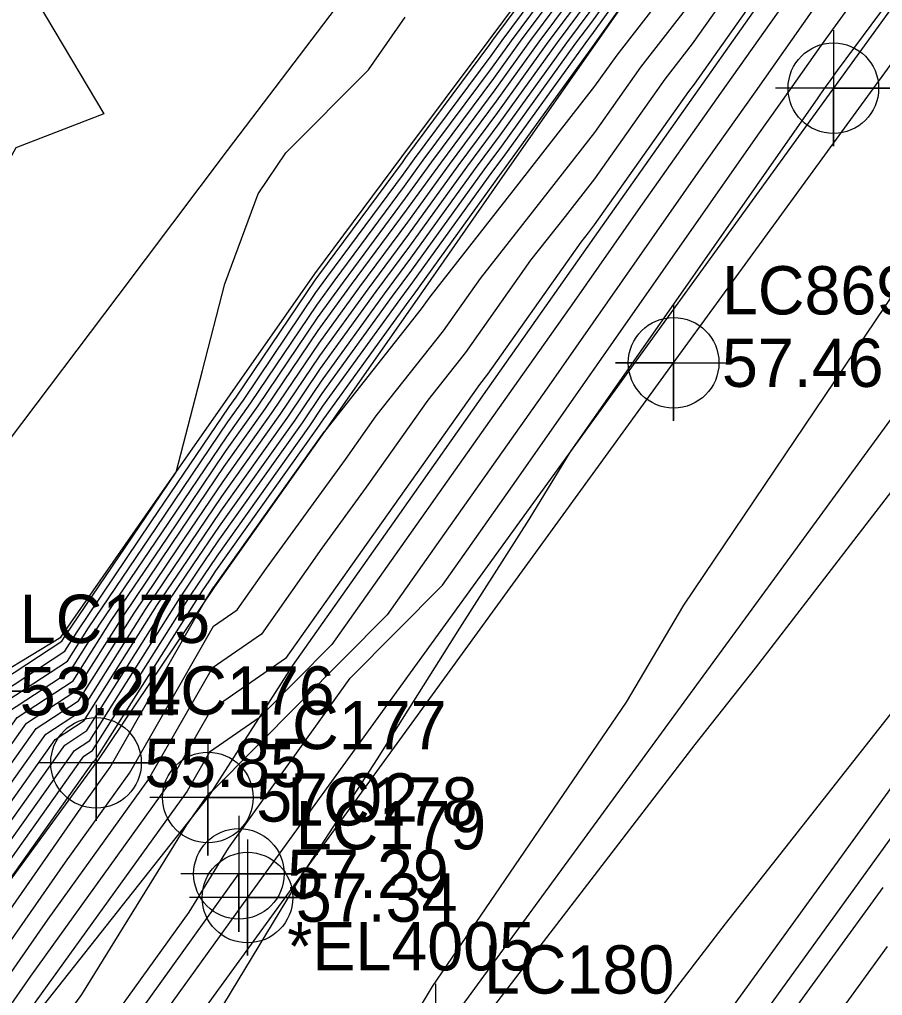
# Model space of a CAD drawing. Extents: x 2188792 to 2191981, y 386090 to 389710.
# Drawn here: x 2190183 to 2190227.7, y 387712.4 to 387762.9 of the extents above; entities that cross this region are included whole.
import ezdxf

# ---------------------------------------------------------------- set-up
doc = ezdxf.new("R2010")
doc.units = 0
for name, color, linetype in [('DTM Contours Major', 7, 'Continuous'), ('DTM Contours Minor', 7, 'Continuous'), ('Exist DTM Breakline', 7, 'Continuous'), ('Exist DTM Breakline Cogo Comment', 7, 'Continuous'), ('Exist DTM Breakline Cogo Elevation', 7, 'Continuous'), ('Exist DTM Breakline Cogo Number', 7, 'Continuous'), ('Exist DTM Breakline Cogo Point CELL', 7, 'Continuous'), ('Exist Roads EOP', 7, 'Continuous'), ('Exist Roads EOP Cogo Elevation', 7, 'Continuous'), ('Exist Roads EOP Cogo Number', 7, 'Continuous'), ('Exist Roads EOP Cogo Point CELL', 7, 'Continuous'), ('Exist Roads EOT', 7, 'Continuous'), ('Exist Roads EOT Cogo Elevation', 7, 'Continuous'), ('Exist Roads EOT Cogo Number', 7, 'Continuous'), ('Exist Roads EOT Cogo Point CELL', 7, 'Continuous'), ('PH Exist DTM Breakline', 7, 'Continuous')]:
    doc.layers.add(name, color=color, linetype=linetype)

msp = doc.modelspace()

# ---------------------------------------------------------------- linework, layer by layer
at = {"layer": 'DTM Contours Major'}
for points in [[(2190133.87, 387655.746), (2190142.758, 387668.494), (2190149.725, 387678.572), (2190158.031, 387690.49), (2190165.915, 387701.499), (2190174.768, 387715.425), (2190179.91, 387723.513), (2190182.41, 387727.03), (2190185.657, 387729.153), (2190187.188, 387731.574), (2190190.393, 387736.313), (2190193.755, 387741.283), (2190194.999, 387743.03), (2190198.413, 387748.085), (2190199.369, 387749.409), (2190202.959, 387754.245), (2190203.928, 387755.588), (2190207.505, 387760.407), (2190208.488, 387761.771), (2190212.052, 387766.571)], [(2190140.89, 387656.284), (2190146.901, 387665.291), (2190154.576, 387676.484), (2190161.876, 387687.503), (2190167.02, 387694.554), (2190179.211, 387712.029), (2190186.322, 387722.222), (2190187.723, 387724.17), (2190192.656, 387732.814), (2190193.092, 387733.504), (2190193.112, 387733.532), (2190193.132, 387733.563), (2190198.6, 387741.243), (2190198.822, 387741.549), (2190198.826, 387741.554), (2190203.838, 387747.893), (2190204.285, 387748.526), (2190208.885, 387754.4), (2190212.816, 387759.42), (2190213.956, 387761.034), (2190217.629, 387765.763)], [(2190127.342, 387642.535), (2190141.894, 387663.608), (2190144.416, 387667.226), (2190156.401, 387684.564), (2190159.664, 387689.245), (2190172.917, 387707.751), (2190176.812, 387713.878), (2190179.075, 387717.436), (2190184.882, 387725.608), (2190186.377, 387726.585), (2190190.14, 387732.539), (2190191.753, 387734.923), (2190193.444, 387737.423), (2190196.91, 387742.291), (2190198.616, 387744.818), (2190201.494, 387748.804), (2190203.232, 387751.146), (2190206.18, 387755.233), (2190207.853, 387757.486), (2190210.876, 387761.68), (2190212.479, 387763.839)], [(2190224.046, 387763.305), (2190221.103, 387759.138), (2190218.148, 387754.954), (2190210.306, 387743.744), (2190207.567, 387739.867), (2190204.816, 387735.972), (2190202.053, 387732.06), (2190192.984, 387722.924), (2190192.787, 387722.788), (2190192.698, 387722.633), (2190191.665, 387721.196), (2190186.235, 387712.417), (2190183.515, 387708.629), (2190176.737, 387698.177), (2190166.485, 387683.901), (2190161.021, 387675.685), (2190151.311, 387661.898), (2190146.496, 387654.704)], [(2190170.079, 387637.175), (2190184.662, 387656.987), (2190185.776, 387658.366), (2190186.967, 387659.84), (2190188.243, 387661.42), (2190197.783, 387674.451), (2190199.179, 387676.153), (2190200.634, 387677.925), (2190213.842, 387695.932), (2190215.385, 387697.799), (2190216.994, 387699.745), (2190218.456, 387701.786), (2190227.964, 387714.893)]]:
    msp.add_lwpolyline(points, dxfattribs=at)
at = {"layer": 'DTM Contours Minor'}
for points in [[(2190236.814, 387775.68), (2190225.355, 387760.234), (2190225.027, 387759.78), (2190224.687, 387759.299), (2190224.346, 387758.816), (2190211.532, 387740.5), (2190209.395, 387737.001), (2190205.804, 387731.38), (2190201.546, 387724.601), (2190197.585, 387718.517), (2190188.492, 387703.504), (2190186.127, 387699.811), (2190174.426, 387684.183), (2190172.877, 387681.712), (2190156.767, 387660.35), (2190155.266, 387658.13), (2190146.358, 387642.623)], [(2190180.149, 387770.153), (2190187.392, 387758.002), (2190182.84, 387756.231), (2190180.027, 387751.126), (2190177.184, 387749.402), (2190173.952, 387743.892), (2190171.784, 387742.264), (2190161.749, 387741.818), (2190161.042, 387741.424), (2190160.579, 387741.13), (2190160.248, 387740.921), (2190159.124, 387741.951), (2190160.03, 387742.776), (2190160.137, 387742.776), (2190160.326, 387742.976), (2190168.506, 387745.64), (2190168.822, 387746.292), (2190169.721, 387748.153), (2190173.552, 387753.544), (2190174.832, 387756.785), (2190178.103, 387761.247), (2190180.12, 387770.172)], [(2190131.832, 387646.855), (2190145.085, 387666.714), (2190145.132, 387666.783), (2190145.306, 387667.046), (2190159.072, 387686.961), (2190160.317, 387688.747), (2190175.718, 387710.251), (2190177.63, 387713.259), (2190178.74, 387715.006), (2190185.871, 387725.04), (2190186.665, 387725.558), (2190191.321, 387732.925), (2190192.296, 387734.367), (2190193.319, 387735.879), (2190197.674, 387741.996), (2190198.698, 387743.511), (2190202.344, 387748.563), (2190203.342, 387749.906), (2190207.081, 387755.091), (2190207.992, 387756.318), (2190211.831, 387761.644), (2190212.65, 387762.746), (2190216.595, 387768.222)], [(2190134.852, 387649.998), (2190145.69, 387666.24), (2190148.28, 387670.017), (2190157.797, 387684.383), (2190160.408, 387688.159), (2190160.644, 387688.498), (2190177.118, 387711.502), (2190178.039, 387712.95), (2190178.573, 387713.791), (2190186.366, 387724.755), (2190186.809, 387725.045), (2190191.911, 387733.118), (2190192.568, 387734.089), (2190193.257, 387735.107), (2190198.056, 387741.848), (2190198.738, 387742.858), (2190202.769, 387748.442), (2190203.396, 387749.287), (2190207.532, 387755.02), (2190208.062, 387755.733), (2190212.309, 387761.625), (2190212.735, 387762.199), (2190217.101, 387768.26)], [(2190243.271, 387768.482), (2190235.055, 387757.448), (2190228.888, 387749.601), (2190217.395, 387732.559), (2190214.432, 387727.547), (2190204.397, 387712.818), (2190202.052, 387708.946), (2190187.254, 387685.834), (2190204.7, 387708.079), (2190206.378, 387710.213), (2190218.002, 387725.342), (2190221.117, 387729.294), (2190235.868, 387748.461), (2190239.037, 387752.903), (2190247.964, 387765.605)], [(2190130.661, 387652.601), (2190142.095, 387669.001), (2190147.054, 387676.176), (2190157.378, 387690.988), (2190163.115, 387698.998), (2190173.951, 387716.044), (2190180.244, 387725.943), (2190181.421, 387727.599), (2190185.37, 387730.18), (2190186.007, 387731.189), (2190189.85, 387736.869), (2190193.88, 387742.827), (2190194.235, 387743.326), (2190198.332, 387749.392), (2190198.519, 387749.651), (2190202.849, 387755.484), (2190203.027, 387755.731), (2190207.365, 387761.575), (2190207.533, 387761.808), (2190211.881, 387767.664)], [(2190132.265, 387654.173), (2190142.426, 387668.748), (2190148.389, 387677.374), (2190157.705, 387690.739), (2190164.515, 387700.248), (2190174.36, 387715.734), (2190180.077, 387724.728), (2190181.915, 387727.314), (2190185.514, 387729.667), (2190186.598, 387731.382), (2190190.121, 387736.591), (2190193.817, 387742.055), (2190194.617, 387743.178), (2190198.373, 387748.739), (2190198.944, 387749.53), (2190202.904, 387754.865), (2190203.477, 387755.659), (2190207.435, 387760.991), (2190208.011, 387761.79), (2190211.966, 387767.118)], [(2190221.595, 387766.921), (2190217.846, 387761.61), (2190216.427, 387759.784), (2190212.792, 387754.636), (2190211.267, 387752.689), (2190209.484, 387750.412), (2190206.117, 387745.647), (2190204.166, 387743.179), (2190200.98, 387738.67), (2190198.686, 387735.506), (2190195.547, 387731.064), (2190192.994, 387729.304), (2190189.713, 387723.555), (2190184.502, 387716.311), (2190180.69, 387710.847), (2190174.155, 387701.479), (2190163.184, 387686.443), (2190160.871, 387682.952), (2190148.112, 387664.343), (2190146.929, 387662.57), (2190131.187, 387639.658)], [(2190222.869, 387766.495), (2190217.954, 387759.534), (2190217.663, 387759.159), (2190212.779, 387752.243), (2190212.459, 387751.834), (2190212.083, 387751.355), (2190207.257, 387744.523), (2190206.837, 387743.992), (2190202.059, 387737.231), (2190201.553, 387736.533), (2190196.795, 387729.8), (2190192.925, 387727.132), (2190190.708, 387723.248), (2190183.592, 387713.356), (2190181.43, 387710.256), (2190177.722, 387704.941), (2190164.766, 387687.184), (2190164.244, 387686.379), (2190163.885, 387685.879), (2190150.972, 387666.462), (2190148.998, 387663.661), (2190136.26, 387644.629)], [(2190125.988, 387643.58), (2190135.475, 387657.318), (2190143.09, 387668.24), (2190151.06, 387679.771), (2190158.358, 387690.241), (2190167.316, 387702.749), (2190175.177, 387715.116), (2190179.743, 387722.297), (2190182.904, 387726.746), (2190185.801, 387728.64), (2190187.778, 387731.767), (2190190.665, 387736.035), (2190193.693, 387740.511), (2190195.381, 387742.882), (2190198.454, 387747.432), (2190199.794, 387749.288), (2190203.013, 387753.625), (2190204.378, 387755.517), (2190207.574, 387759.823), (2190208.966, 387761.753), (2190212.137, 387766.025)], [(2190126.326, 387643.319), (2190137.08, 387658.89), (2190143.421, 387667.987), (2190152.395, 387680.969), (2190158.684, 387689.992), (2190168.716, 387703.999), (2190175.586, 387714.806), (2190179.576, 387721.082), (2190183.399, 387726.461), (2190185.945, 387728.126), (2190188.369, 387731.96), (2190190.937, 387735.757), (2190193.631, 387739.739), (2190195.764, 387742.735), (2190198.495, 387746.778), (2190200.219, 387749.167), (2190203.068, 387753.005), (2190204.829, 387755.446), (2190207.644, 387759.238), (2190209.443, 387761.735), (2190212.223, 387765.478)], [(2190223.556, 387765.067), (2190219.311, 387759.057), (2190215.049, 387753.023), (2190211.731, 387748.279), (2190207.569, 387742.387), (2190203.388, 387736.468), (2190199.189, 387730.522), (2190195.427, 387726.733), (2190192.856, 387724.96), (2190191.703, 387722.941), (2190182.683, 387710.4), (2190182.169, 387709.665), (2190181.29, 387708.404), (2190178.215, 387704.19), (2190170.49, 387692.278), (2190165.185, 387684.89), (2190155.996, 387671.074), (2190150.155, 387662.779), (2190141.378, 387649.667)], [(2190126.665, 387643.058), (2190138.684, 387660.463), (2190143.753, 387667.733), (2190153.731, 387682.167), (2190159.011, 387689.743), (2190170.117, 387705.25), (2190175.995, 387714.497), (2190179.409, 387719.867), (2190183.893, 387726.177), (2190186.089, 387727.612), (2190188.959, 387732.153), (2190191.209, 387735.479), (2190193.568, 387738.967), (2190196.146, 387742.587), (2190198.535, 387746.125), (2190200.644, 387749.046), (2190203.123, 387752.386), (2190205.279, 387755.375), (2190207.714, 387758.654), (2190209.921, 387761.717), (2190212.308, 387764.932)], [(2190127.003, 387642.796), (2190140.289, 387662.035), (2190144.085, 387667.479), (2190155.066, 387683.366), (2190159.337, 387689.494), (2190171.517, 387706.5), (2190176.404, 387714.187), (2190179.242, 387718.652), (2190184.388, 387725.893), (2190186.233, 387727.099), (2190189.55, 387732.346), (2190191.481, 387735.201), (2190193.506, 387738.195), (2190196.528, 387742.439), (2190198.576, 387745.471), (2190201.069, 387748.925), (2190203.177, 387751.766), (2190205.73, 387755.304), (2190207.783, 387758.07), (2190210.399, 387761.698), (2190212.393, 387764.385)], [(2190130.575, 387640.019), (2190143.91, 387659.427), (2190147.506, 387664.817), (2190157.723, 387679.718), (2190162.53, 387686.973), (2190170.587, 387698.016), (2190179.951, 387711.438), (2190185.412, 387719.266), (2190188.718, 387723.862), (2190193.063, 387731.476), (2190194.3, 387732.329), (2190195.82, 387734.479), (2190199.901, 387740.11), (2190201.496, 387742.367), (2190204.978, 387746.77), (2190206.884, 387749.469), (2190210.076, 387753.544), (2190212.804, 387757.028), (2190215.192, 387760.409), (2190217.737, 387763.686)], [(2190137.871, 387653.141), (2190146.296, 387665.766), (2190151.428, 387673.251), (2190161.221, 387688.033), (2190163.453, 387691.092), (2190178.471, 387712.62), (2190180.248, 387715.167), (2190186.86, 387724.471), (2190186.953, 387724.531), (2190192.502, 387733.311), (2190192.84, 387733.81), (2190193.194, 387734.335), (2190198.438, 387741.7), (2190198.779, 387742.204), (2190203.194, 387748.321), (2190203.451, 387748.667), (2190207.983, 387754.949), (2190208.131, 387755.149), (2190212.786, 387761.607), (2190212.82, 387761.653), (2190214.159, 387763.512)], [(2190139.311, 387642.336), (2190151.615, 387659.742), (2190152.468, 387661.017), (2190166.045, 387680.296), (2190167.785, 387682.911), (2190182.984, 387704.076), (2190185.135, 387707.394), (2190191.803, 387716.678), (2190193.847, 387719.984), (2190200.144, 387728.79), (2190204.917, 387733.598), (2190206.245, 387735.476), (2190207.566, 387737.347), (2190208.881, 387739.209), (2190221.247, 387756.885), (2190222.895, 387759.218), (2190224.536, 387761.542), (2190226.123, 387763.736)], [(2190089.046, 387592.183), (2190094.223, 387599.782), (2190102.776, 387612.43), (2190110.974, 387624.441), (2190120.573, 387638.672), (2190124.634, 387644.626), (2190129.056, 387651.028), (2190141.763, 387669.255), (2190145.718, 387674.977), (2190157.052, 387691.237), (2190161.714, 387697.747), (2190173.542, 387716.353), (2190180.411, 387727.159), (2190180.926, 387727.883), (2190185.226, 387730.694), (2190185.417, 387730.996), (2190189.578, 387737.147), (2190191.136, 387739.451), (2190192.499, 387744.704), (2190193.664, 387749.189), (2190195.374, 387753.85), (2190196.814, 387755.98), (2190201.094, 387760.265), (2190202.983, 387762.997)], [(2190132.815, 387649.709), (2190143.499, 387665.18), (2190144.748, 387666.972), (2190157.737, 387685.762), (2190159.991, 387688.996), (2190174.318, 387709.001), (2190177.221, 387713.568), (2190178.907, 387716.221), (2190185.377, 387725.324), (2190186.521, 387726.072), (2190190.731, 387732.732), (2190192.024, 387734.645), (2190193.381, 387736.651), (2190197.292, 387742.143), (2190198.657, 387744.165), (2190201.919, 387748.683), (2190203.287, 387750.526), (2190206.631, 387755.162), (2190207.922, 387756.902), (2190211.354, 387761.662), (2190212.564, 387763.292)], [(2190065.514, 387514.559), (2190081.303, 387536.264), (2190082.63, 387538.282), (2190097.61, 387559.851), (2190098.692, 387561.489), (2190115.183, 387585.188), (2190115.572, 387585.629), (2190129.097, 387601.222), (2190133.281, 387605.947), (2190145.736, 387620.245), (2190151.288, 387627.466), (2190156.609, 387634.62), (2190165.07, 387645.609), (2190174.107, 387657.741), (2190181.981, 387667.906), (2190187.788, 387675.299), (2190199.057, 387689.861), (2190205.414, 387697.968), (2190216.141, 387711.606), (2190219.575, 387716.076), (2190234.549, 387735.079)], [(2190227.714, 387717.942), (2190215.973, 387701.758), (2190215.441, 387701.015), (2190214.856, 387700.307), (2190214.294, 387699.628), (2190198.093, 387677.541), (2190197.668, 387677.022), (2190197.259, 387676.524), (2190185.671, 387660.695), (2190185.373, 387660.327), (2190185.096, 387659.984), (2190184.837, 387659.663), (2190167.502, 387636.111)]]:
    msp.add_lwpolyline(points, dxfattribs=at)
at = {"layer": 'Exist DTM Breakline'}
for points in [[(2189992.243, 387453.105), (2190028.023, 387502.725), (2190063.31, 387551.461), (2190096.85, 387598.566), (2190127.537, 387642.384), (2190160.72, 387688.44), (2190186.991, 387724.396)], [(2189995.924, 387449.921), (2190033.109, 387498.748), (2190066.603, 387548.559), (2190100.696, 387595.155), (2190131.134, 387639.583), (2190163.791, 387685.951), (2190192.781, 387722.608)], [(2189998.889, 387447.645), (2190035.636, 387497.082), (2190069.466, 387545.534), (2190104.367, 387592.678), (2190135.108, 387636.538), (2190168.392, 387682.449), (2190194.386, 387718.656)]]:
    msp.add_lwpolyline(points, dxfattribs=at)
at = {"layer": 'Exist DTM Breakline Cogo Point CELL'}
for points in [[(2190180.541, 387731.105), (2190180.541, 387725.105), (2190180.541, 387728.105), (2190183.541, 387728.105), (2190177.541, 387728.105)], [(2190186.991, 387727.396), (2190186.991, 387721.396), (2190186.991, 387724.396), (2190189.991, 387724.396), (2190183.991, 387724.396)], [(2190192.781, 387725.608), (2190192.781, 387719.608), (2190192.781, 387722.608), (2190195.781, 387722.608), (2190189.781, 387722.608)], [(2190194.386, 387721.656), (2190194.386, 387715.656), (2190194.386, 387718.656), (2190197.386, 387718.656), (2190191.386, 387718.656)]]:
    msp.add_lwpolyline(points, dxfattribs=at)
for centre in [(2190186.991, 387724.396), (2190192.781, 387722.608), (2190194.386, 387718.656)]:
    msp.add_circle(centre, 2.344, dxfattribs=at)
at = {"layer": 'Exist Roads EOP'}
for points in [[(2190313.986, 387884.141), (2190285.547, 387843.636), (2190254.588, 387800.045), (2190225.155, 387759.32), (2190194.829, 387717.425), (2190164.291, 387675.101), (2190137.229, 387637.301), (2190105.098, 387592.774), (2190071.411, 387546.221), (2190039.296, 387501.568), (2190007.542, 387457.958), (2189976.844, 387415.407), (2189936.359, 387359.145), (2189907.138, 387318.716), (2189868.636, 387265.243), (2189836.428, 387220.463), (2189805.695, 387177.815), (2189775.592, 387135.957), (2189745.498, 387094.055), (2189715.496, 387052.249), (2189683.869, 387008.07), (2189653.218, 386965.867), (2189623.729, 386924.667)], [(2190335.128, 387868.989), (2190306.373, 387829.271), (2190274.581, 387784.921), (2190245.133, 387744.071), (2190214.553, 387701.741), (2190184.89, 387660.475), (2190157.493, 387622.204), (2190126.048, 387578.501), (2190091.216, 387530.568), (2190059.634, 387486.726), (2190026.932, 387441.783), (2189997.689, 387401.032), (2189957.023, 387344.154), (2189927.908, 387303.922), (2189889.008, 387250.224), (2189856.606, 387205.5), (2189825.68, 387162.612), (2189795.668, 387120.822), (2189765.955, 387079.619), (2189734.998, 387036.704), (2189703.849, 386993.356), (2189673.984, 386951.979), (2189643.253, 386909.427)]]:
    msp.add_lwpolyline(points, dxfattribs=at)
at = {"layer": 'Exist Roads EOP Cogo Point CELL'}
for points in [[(2190225.155, 387762.32), (2190225.155, 387756.32), (2190225.155, 387759.32), (2190228.155, 387759.32), (2190222.155, 387759.32)], [(2190194.829, 387720.425), (2190194.829, 387714.425), (2190194.829, 387717.425), (2190197.829, 387717.425), (2190191.829, 387717.425)]]:
    msp.add_lwpolyline(points, dxfattribs=at)
for centre in [(2190225.155, 387759.32), (2190194.829, 387717.425)]:
    msp.add_circle(centre, 2.344, dxfattribs=at)
at = {"layer": 'Exist Roads EOT'}
for points in [[(2189910.407, 387320.236), (2189942.075, 387364.22), (2189970.438, 387403.768), (2190000.916, 387446.161), (2190032.053, 387489.248), (2190063.107, 387532.142), (2190093.978, 387574.79), (2190125.104, 387617.946), (2190155.102, 387659.638), (2190185.949, 387702.484), (2190216.886, 387745.11), (2190247.602, 387787.3), (2190276.876, 387828.015), (2190303.928, 387865.67), (2190323.039, 387892.195)], [(2190333.162, 387868.755), (2190301.785, 387825.12), (2190269.645, 387780.315), (2190237.827, 387736.49), (2190205.816, 387692.275), (2190173.845, 387647.822), (2190143.211, 387605.324), (2190112.772, 387563.076), (2190082.117, 387520.492), (2190050.947, 387477.405), (2190019.959, 387434.524), (2189989.253, 387391.986)], [(2190295.87, 387836.508), (2190264.435, 387792.457), (2190235.289, 387751.997), (2190204.567, 387709.955), (2190174.375, 387667.889)]]:
    msp.add_lwpolyline(points, dxfattribs=at)
at = {"layer": 'Exist Roads EOT Cogo Point CELL'}
for points in [[(2190216.886, 387748.11), (2190216.886, 387742.11), (2190216.886, 387745.11), (2190213.886, 387745.11), (2190219.886, 387745.11)], [(2190204.567, 387712.955), (2190204.567, 387706.955), (2190204.567, 387709.955), (2190201.567, 387709.955), (2190207.567, 387709.955)]]:
    msp.add_lwpolyline(points, dxfattribs=at)
msp.add_circle((2190216.886, 387745.11), 2.344, dxfattribs=at)
at = {"layer": 'PH Exist DTM Breakline'}
for points in [[(2190180.541, 387728.105), (2190185.164, 387730.913), (2190189.547, 387737.179), (2190193.93, 387743.444), (2190198.312, 387749.71), (2190202.825, 387755.762), (2190207.337, 387761.815), (2190211.849, 387767.868), (2190216.361, 387773.921), (2190220.896, 387780.569), (2190225.431, 387787.218), (2190229.965, 387793.866), (2190234.643, 387800.015), (2190239.32, 387806.163), (2190243.998, 387812.312), (2190248.218, 387818.171), (2190252.438, 387824.03), (2190256.658, 387829.889), (2190260.816, 387836.07), (2190265.791, 387842.926), (2190270.765, 387849.782)], [(2190276.671, 387848.261), (2190271.748, 387840.263), (2190267.321, 387835.092), (2190262.893, 387829.922), (2190257.613, 387823.753), (2190252.334, 387817.584), (2190248.364, 387811.956), (2190244.395, 387806.329), (2190240.426, 387800.701), (2190235.861, 387794.269), (2190231.296, 387787.838), (2190226.731, 387781.406), (2190222.167, 387774.974), (2190217.497, 387768.29), (2190212.828, 387761.606), (2190208.158, 387754.921), (2190203.489, 387748.237), (2190198.82, 387741.552), (2190193.128, 387733.515), (2190186.991, 387724.396)], [(2190267.624, 387828.086), (2190262.809, 387821.487), (2190257.994, 387814.888), (2190253.179, 387808.289), (2190248.364, 387801.69), (2190243.55, 387795.091), (2190238.459, 387787.916), (2190233.369, 387780.74), (2190228.278, 387773.565), (2190223.188, 387766.389), (2190217.982, 387758.998), (2190212.776, 387751.606), (2190207.57, 387744.215), (2190202.364, 387736.823), (2190197.159, 387729.432), (2190192.781, 387722.608)], [(2190199.702, 387763.888), (2190193.786, 387756.089), (2190188.113, 387748.568), (2190182.441, 387741.046), (2190176.768, 387733.525), (2190171.096, 387726.004), (2190165.726, 387717.922), (2190160.357, 387709.841), (2190154.987, 387701.759), (2190149.617, 387693.678), (2190144.248, 387685.596), (2190140.026, 387679.691), (2190135.804, 387673.786), (2190131.582, 387667.881), (2190127.329, 387662.149), (2190123.076, 387656.418), (2190118.824, 387650.686)]]:
    msp.add_lwpolyline(points, dxfattribs=at)

# ---------------------------------------------------------------- texts
at = {"layer": 'Exist DTM Breakline Cogo Comment'}
msp.add_text('*EL4005', height=2.5, dxfattribs=at).set_placement((2190196.886, 387713.656))
at = {"layer": 'Exist DTM Breakline Cogo Elevation'}
for s, p in [('53.24', (2190183.041, 387726.855)), ('55.85', (2190189.491, 387723.146)), ('57.02', (2190195.281, 387721.358)), ('57.29', (2190196.886, 387717.406))]:
    msp.add_text(s, height=2.5, dxfattribs=at).set_placement(p)
at = {"layer": 'Exist DTM Breakline Cogo Number'}
for s, p in [('LC175', (2190183.041, 387730.605)), ('LC176', (2190189.491, 387726.896)), ('LC177', (2190195.281, 387725.108)), ('LC178', (2190196.886, 387721.156))]:
    msp.add_text(s, height=2.5, dxfattribs=at).set_placement(p)
at = {"layer": 'Exist Roads EOP Cogo Elevation'}
msp.add_text('57.34', height=2.5, dxfattribs=at).set_placement((2190197.329, 387716.175))
at = {"layer": 'Exist Roads EOP Cogo Number'}
msp.add_text('LC179', height=2.5, dxfattribs=at).set_placement((2190197.329, 387719.925))
at = {"layer": 'Exist Roads EOT Cogo Elevation'}
msp.add_text('57.46', height=2.5, dxfattribs=at).set_placement((2190219.386, 387743.86))
at = {"layer": 'Exist Roads EOT Cogo Number'}
for s, p in [('LC869', (2190219.386, 387747.61)), ('LC180', (2190207.067, 387712.455))]:
    msp.add_text(s, height=2.5, dxfattribs=at).set_placement(p)

doc.saveas('drawing.dxf')
